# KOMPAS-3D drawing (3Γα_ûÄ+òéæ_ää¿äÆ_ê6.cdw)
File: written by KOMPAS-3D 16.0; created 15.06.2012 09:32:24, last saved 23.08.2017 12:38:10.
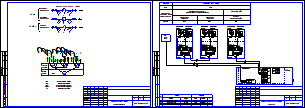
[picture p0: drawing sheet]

Sheets 1-2: A3, landscape

Title block, sheet 1: name: Руководство по эксплуатации; sheet number: 1; sheets: 27; organisation: ООО"Интелприбор"; sheet format: A3; stored path: W:\Users\smirnov_v\Desktop\шаблоны\4-х трубка\4-х трубка ГВС-max.cdw / D:\Проекты\Лыткарино\ул. Квартал 3А, д.25\710.74 РП.cdw; file name: 4-х трубка ГВС-max.cdw / 710.74 РП.cdw; cell 51: МО, Воскресенсикй р-н, п. Хорлово, ул. Интернациональная, д. 4; cell 320: Р
Title block, sheet 2: sheet number: 2

Views: Вид 2, Вид 3
Referenced files in C:\Program Files (x86)\ASCON\KOMPAS-3D V16\Sys\: spds.lcs, EngSys.lcs, GRAPHIC.LHS
Referenced files: graphic.tdp
Referenced files in W:\Users\smirnov_v\Desktop\шаблоны\4-х трубка\: 4-х трубка ГВС-max.cdw
Referenced files in D:\Проекты\Лыткарино\ул. Квартал 3А, д.25\: 710.74 РП.cdw
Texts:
  Смирнов В.С.
  УУ-3423
  GOST Common
  Normal
  List Paragraph
  heading 3
  для схемы
  txt
  Т0-элементы
  ВРУ
  каб.
  Начало
  трассы
  Трассы
  Марка
  Проложен
  Изм. модуль (Т1)
  Изм. модуль (Т2)
  Изм. модуль (В1)
  ВРУ 220В, 50 Гц
  СБ МКТС
  ИМ (Т1)
  FTP
  ПВС
  Конец
  Кол-во и
  сеч. жил
  Длина,
  Агрегат
  Системный блок  МКТС
  Среда
  Вода
  параметра и место
  отбора импульса
  Учет тепловой энергии и
  теплоносителя системы отопления
  Подающий
  трубопровод
  отопления
  Обратный
  Узел учета ХВС
  Вводной
  трубопровод ХВС
  ИМ1
  ИМ2
  ИМ3
  Плата подключений
  UP+
  UP-
  ИМП
  Лин
  Измерительный
  модуль М121
  Pt 100
  Преобразователь
  температуры
  давления
  Преобразователь расхода
  Термопреобразователь
  Преобразователь давления
  Преобразователь цифровой
  Системный блок МКТС
  приборы
  по месту
  шкаф
  учета
  UQIES
  УУТЭ
  Функциональная схема
  УУХВС
  Размеры, параметризация
  сит. план
  подача ГВС
  обратка ГВС
  хвс
  обратка
  POLYLINE_STYLE_0.25_RGB_0_0_0
  стены
  Основная (не является границей для штриховки)
  POLYLINE_STYLE_0.18_RGB_0_0_0
  ХВС
  зеленая
  Красная тонкая
  арматура
  Подача
  Скрытая линия
  Ось Z
  Ось Y
  Ось X
  Образующая трубопровода (проектируемого)
  Трубопровод толщиной 0.6мм (одна линия)
  Трубопровод толщиной 1.2мм (одна линия)
  Трубопровод толщиной 1.0мм (одна линия)
  Трубопровод толщиной 0.8мм (одна линия)
  Трубопровод существующий (одна линия)
  Трубопровод невидимый (одна линия)
  Трубопровод демонтируемый (одна линия)
  Осевая трубопровода
  Осевая трубопровода (демонтируемого)
  Образующая трубопровода (существующего)
  Образующая трубопровода (невидимого)
  Изолированный трубопровод проектируемый (одна линия)
  Изолированный трубопровод существующий (одна линия)
  Образующая изоляции
  Изоляция
  Изолированный трубопровод невидимый (одна линия)
  Штрих пвс 075
  штрих пвс 2,5
  существующее оборудование
  Существующее оборудование
  K5LT_BASIC_RGB_0_0_255_THICK_0.53
  POLYLINE_STYLE_1.51_RGB_0_0_255
  POLYLINE_STYLE_0.50_RGB_128_128_128
  K5LT_AXLED_RGB_255_128_0_SC_1_THICK_0.18
  ACAD_ISO04W100_RGB_0_0_0_SC_1_THICK_0.18
  тонкая черная
  тонкая красная
  тонкая синяя
  тонкая оранж
  красн штрих
  пломбировка
  Провода
  синий штрих
  Стили документа
  G2co
  расход вторичной воды объемный
  расход вторичной воды объемный при 70гр
  Gco
  расход теплоносителя массовый
  расход теплоносит объемн подающ
  расход теплоносит объемн обр
  Лапир
  Ghvs
  Im1
  Im2
  Im3
  Im4
  Im5
  Khvs
  норматив ХВС
  число подъездов
  число этажей
  Nkv
  число квартир
  тепловая нагрузка на отопление
  сумма Q
  Qgvs
  тепловая нагрузка ГВС
  тепловая нагрузка на циркуляцию ГВС
  иммитовставка или под манометр
  ro1
  ro2
  ro3
  ro4
  верх предел темп граф
  нижн предел темп граф
  темп подачи ГВС
  темп обр ГВС
  темр хол воды
  vzdh
  Kchn
  Ktp
  Knp
  tnv
  Vклап
  KLP
  RPD
  RDS
  PUMP
  ro5
  beta
  tnv98
  Shifr
  Переход ГОСТ 17378-2001
  Переход
  ГОСТ
  Сталь 09Г2С ГОСТ 19281-89
  Втулка 20x50
  Лит-Масса-Масштаб
  Материал-Предприятие
  Title Specification
  Body Specification ( left align )
  Body Specificaton ( centered )
  Поз.
  Кол.
  Приме-
  чание
  Таблица спецификации
  Засыпка
  Штрих3
  Штрих2
  Штрих1
  Песок
  Штр0.5пр7
  Штр0.5пр12
  Штр0.3пр10
  Штр1.4пр21.21
  Штр1пр15
  Штр2.12пр35
  Штр1.5пр25
  Штр2.82пр42.42
  Штр2пр30
  SACNCR_ISO 1
  Электрощитовая
  Пр-1
  Ок-1
  Обозначение стандарта
  Типоразмер
  Пояснительная записка
  автоматизации
  Рабочие чертежи основного комплекта. ГОСТ Р 21.1101-2009 Ф3
  Стадия
  Лист
  Листов
  Изм.
  Кол.уч.
  №док.
  Подп.
  Дата
  Разраб.
  Пров.
  Т.контр.
  Н.контр.
  Утв.
  Изменение
  Номер документа
  Подпись
  Наименование объекта строительства, в состав которого входит здание, наим. микр
  Наименование здания (сооружения)
  Порядковый номер листа
  Количество листов в документе
  Наименование изображения
  Индекс предприятия, выпускающего документ
  Инв. № подл.
  Подп. и дата
  Взам. инв. №
  Инвентарный номер подлинника
  Подпись принявшего подлинник на хранение
  Инвентарный номер подлинника, взамен которого выпущен данный подлинник
  Согласовано
  Формат листа
  Согласование
  03 Рабочие чертежи основного комплекта. ГОСТ Р 21.1101-2009 Ф3
  Схема соединений внешних
  проводок
Dimensions and other numbers on the sheet: 220В; 50Гц; 2x2x0,52; 3х0,75; 5; 2; 1; 3; 6; 4; 4-20; 13; 1,2,3; 4,5,6; 7,8,9; 10,11,12; 8; 10; 11; 7; 12; 5,0; 3,2388; 0,0400; 40; 95; 3,1876; 4,5; 70; 9; 0,0; 0,0000; 0; 09Г2С; 20; 27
